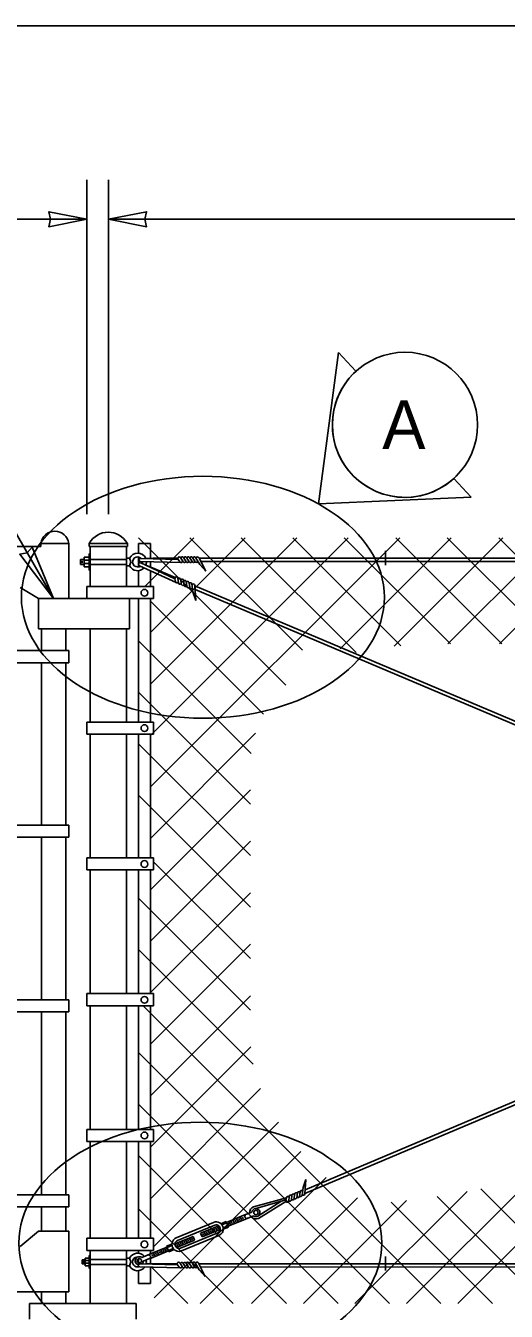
# Model space of a CAD drawing. Extents: x 99862 to 104211, y 98939 to 105076.
# Drawn here: x 101409 to 101607, y 100336 to 100867 of the extents above; entities that cross this region are included whole.
import ezdxf

# ---------------------------------------------------------------- set-up
doc = ezdxf.new("R2010")
doc.units = 0
for name, color, linetype in [('Level 11', 7, 'Continuous'), ('Level 15', 7, 'Continuous'), ('Level 2', 7, 'Continuous'), ('Level 20', 7, 'Continuous'), ('Level 4', 7, 'Continuous'), ('Level 7', 7, 'Continuous'), ('Level 9', 7, 'Continuous')]:
    doc.layers.add(name, color=color, linetype=linetype)

msp = doc.modelspace()

# ---------------------------------------------------------------- linework, layer by layer
at = {"layer": 'Level 11'}
for centre in [(101481.98, 100630.91), (101480.9, 100363.87)]:
    msp.add_ellipse(centre, major_axis=(-75, 0), ratio=0.666667, dxfattribs=at)
at = {"layer": 'Level 15'}
for p, q in [((102151.08, 100867.18), (100287.45, 100867.18)), ((101434.06, 100665.19), (101434.06, 100803.5)), ((101442.98, 100665.19), (101442.98, 100803.5)), ((101434.06, 100787.18), (101009, 100787.18)), ((102151.08, 100787.18), (101442.98, 100787.18)), ((101420.28, 100630.39), (101372.84, 100712.56))]:
    msp.add_line(p, q, dxfattribs=at)
for points in [[(101434.06, 100787.18), (101418.33, 100784.1), (101419.06, 100787.18), (101418.33, 100790.26)], [(101442.98, 100787.18), (101458.7, 100784.1), (101457.97, 100787.18), (101458.7, 100790.26)], [(101420.28, 100630.39), (101411.45, 100651.66), (101409.39, 100649.25), (101406.28, 100648.67)]]:
    msp.add_lwpolyline(points, close=True, dxfattribs=at)
at = {"layer": 'Level 2'}
for p, q in [((101431.33, 100646.54), (101431.33, 100644.46)), ((101431.33, 100646.54), (101432.86, 100646.54)), ((101431.33, 100644.46), (101432.86, 100644.46)), ((101432.14, 100646.02), (101432.14, 100644.98)), ((101432.85, 100644.81), (101434.97, 100644.81)), ((101432.86, 100647.52), (101432.86, 100645.5)), ((101432.86, 100643.48), (101432.86, 100645.5)), ((101432.87, 100646.2), (101434.97, 100646.2)), ((101435.32, 100646.54), (101450.35, 100646.54)), ((101435.32, 100644.46), (101450.35, 100644.46)), ((101451.68, 100647.06), (101452.17, 100645.5)), ((101451.68, 100643.94), (101452.17, 100645.5)), ((101455.74, 100643.96), (101470.93, 100636.94)), ((101456.1, 100645.74), (101472.83, 100645.27)), ((101456.14, 100646.99), (101471.75, 100646.55)), ((101456.26, 100645.1), (101470.44, 100638.55)), ((101458.3, 100646.99), (101461.38, 100647)), ((101458.38, 100644.2), (101461.08, 100643.05)), ((101461.38, 100647), (101471.6, 100647.03)), ((101471.75, 100646.55), (101472.43, 100645.6)), ((101472.75, 100647.29), (101473.76, 100645.57)), ((101473.99, 100647.32), (101475.02, 100645.55)), ((101475.22, 100647.34), (101476.28, 100645.57)), ((101476.46, 100647.36), (101477.49, 100645.64)), ((101477.58, 100645.5), (101477.58, 100645.5)), ((101477.72, 100647.36), (101478.77, 100645.59)), ((101478.98, 100647.34), (101480.66, 100644.48)), ((101480.33, 100647.27), (101483.15, 100641.72)), ((101480.47, 100647), (102110.66, 100647)), ((101480.66, 100644.48), (101483.15, 100641.72)), ((101481.13, 100645.7), (102109.98, 100645.7)), ((101461.08, 100643.05), (101470.49, 100639.04)), ((101470.44, 100638.54), (101470.69, 100637.4)), ((101471.65, 100638.83), (101471.9, 100636.85)), ((101472.8, 100638.36), (101473.06, 100636.33)), ((101473.94, 100637.9), (101474.21, 100635.86)), ((101475.09, 100637.44), (101475.36, 100635.45)), ((101475.38, 100635.28), (101475.38, 100635.28)), ((101476.24, 100636.93), (101476.52, 100634.89)), ((101477.4, 100636.42), (101477.82, 100633.13)), ((101477.82, 100633.13), (101479.01, 100629.61)), ((101478.61, 100635.82), (101479.01, 100629.61)), ((101478.62, 100635.63), (102067.94, 100386.16)), ((101478.72, 100634.17), (102066.84, 100385.21)), ((101796.42, 100499.68), (101524.15, 100384.41)), ((101794.75, 100500.39), (101524.24, 100385.86)), ((101523.36, 100386.85), (101524.51, 100390.25)), ((101524.14, 100384.24), (101524.51, 100390.25)), ((101502.86, 100378.95), (101516.48, 100382.68)), ((101516.25, 100381.57), (101516.48, 100382.68)), ((101517.42, 100381.3), (101517.65, 100383.22)), ((101518.53, 100381.76), (101518.77, 100383.72)), ((101519.63, 100382.21), (101519.89, 100384.19)), ((101520.74, 100382.66), (101521.02, 100384.75)), ((101521.85, 100383.16), (101522.11, 100385.13)), ((101522.97, 100383.66), (101523.36, 100386.85)), ((101503.45, 100378.14), (101516.28, 100381.73)), ((101504.72, 100375.09), (101514.2, 100381.15)), ((101504.91, 100374.12), (101516.3, 100381.09)), ((101470.96, 100366.08), (101486.36, 100372.44)), ((101489.43, 100371.91), (101491.62, 100372.81)), ((101491.62, 100372.81), (101492.57, 100370.5)), ((101491.78, 100372.43), (101498.95, 100375.4)), ((101492.18, 100372.15), (101492.5, 100371.38)), ((101492.41, 100370.89), (101499.59, 100373.86)), ((101492.79, 100372.85), (101493.43, 100371.31)), ((101493.72, 100372.78), (101494.04, 100372.01)), ((101494.33, 100373.49), (101494.97, 100371.95)), ((101495.26, 100373.42), (101495.58, 100372.65)), ((101495.87, 100374.12), (101496.51, 100372.58)), ((101496.8, 100374.06), (101497.12, 100373.29)), ((101497.41, 100374.76), (101498.05, 100373.22)), ((101498.34, 100374.69), (101498.66, 100373.92)), ((101498.95, 100375.4), (101502.24, 100376.75)), ((101499.59, 100373.86), (101502.87, 100375.22)), ((101471.44, 100364.92), (101486.84, 100371.29)), ((101472.71, 100361.84), (101488.12, 100368.21)), ((101473.19, 100360.69), (101488.6, 100367.06)), ((101488.49, 100371.07), (101481, 100367.97)), ((101481, 100367.97), (101481.64, 100366.43)), ((101489.13, 100369.53), (101481.64, 100366.43)), ((101481.93, 100367.91), (101482.25, 100367.14)), ((101482.54, 100368.61), (101483.18, 100367.07)), ((101483.47, 100368.54), (101483.79, 100367.77)), ((101484.08, 100369.25), (101484.72, 100367.71)), ((101485.01, 100369.18), (101485.33, 100368.41)), ((101485.62, 100369.88), (101486.26, 100368.34)), ((101486.55, 100369.82), (101486.87, 100369.05)), ((101487.16, 100370.52), (101487.8, 100368.98)), ((101488.09, 100370.45), (101488.41, 100369.68)), ((101490.39, 100369.6), (101492.57, 100370.5)), ((101467.14, 100362.24), (101459.97, 100359.28)), ((101466.13, 100361.82), (101466.77, 100360.28)), ((101469.16, 100363.53), (101466.98, 100362.63)), ((101466.98, 100362.63), (101467.93, 100360.32)), ((101467.06, 100361.76), (101467.38, 100360.99)), ((101470.43, 100363.6), (101477.92, 100366.7)), ((101471.07, 100362.06), (101478.56, 100365.16)), ((101471.15, 100363.45), (101471.47, 100362.68)), ((101471.76, 100364.15), (101472.4, 100362.61)), ((101472.69, 100364.09), (101473.01, 100363.32)), ((101473.3, 100364.79), (101473.94, 100363.25)), ((101474.23, 100364.72), (101474.55, 100363.95)), ((101474.84, 100365.43), (101475.48, 100363.89)), ((101475.77, 100365.36), (101476.09, 100364.59)), ((101476.38, 100366.06), (101477.02, 100364.52)), ((101477.31, 100366), (101477.63, 100365.23)), ((101477.92, 100366.7), (101478.56, 100365.16)), ((101432.11, 100356.94), (101432.11, 100355.27)), ((101432.11, 100356.94), (101433.33, 100356.94)), ((101432.76, 100356.52), (101432.76, 100355.69)), ((101433.33, 100357.72), (101433.33, 100356.11)), ((101433.33, 100354.49), (101433.33, 100356.11)), ((101433.34, 100356.66), (101435.02, 100356.66)), ((101435.32, 100357.15), (101450.35, 100357.15)), ((101451.68, 100357.67), (101452.16, 100356.11)), ((101451.68, 100354.55), (101452.16, 100356.11)), ((101459.99, 100359.28), (101456.7, 100357.93)), ((101460.63, 100357.75), (101457.34, 100356.39)), ((101467.78, 100360.7), (101460.61, 100357.74)), ((101460.9, 100359.21), (101461.22, 100358.44)), ((101461.51, 100359.91), (101462.15, 100358.37)), ((101462.44, 100359.85), (101462.76, 100359.08)), ((101463.05, 100360.55), (101463.69, 100359.01)), ((101463.98, 100360.48), (101464.3, 100359.71)), ((101464.59, 100361.19), (101465.23, 100359.65)), ((101465.52, 100361.12), (101465.84, 100360.35)), ((101470.12, 100361.22), (101467.93, 100360.32)), ((101432.11, 100355.27), (101433.33, 100355.27)), ((101433.32, 100355.55), (101435.02, 100355.55)), ((101450.35, 100355.07), (101435.32, 100355.07)), ((101455.87, 100354.07), (101472.59, 100353.66)), ((101455.9, 100355.32), (101471.51, 100354.94)), ((101458.53, 100355.33), (101461.13, 100355.35)), ((101461.13, 100355.35), (101471.36, 100355.41)), ((101471.51, 100354.94), (101472.19, 100353.98)), ((101472.51, 100355.68), (101473.52, 100353.96)), ((101473.74, 100355.71), (101474.78, 100353.95)), ((101474.98, 100355.74), (101476.04, 100353.97)), ((101476.21, 100355.77), (101477.34, 100353.91)), ((101477.47, 100355.76), (101478.53, 100354)), ((101478.74, 100355.75), (101480.43, 100352.89)), ((101480.09, 100355.68), (101482.92, 100350.15)), ((101480.26, 100355.34), (102109.78, 100355.28)), ((101480.43, 100352.89), (101482.92, 100350.15)), ((101480.93, 100354.04), (102109.1, 100353.98))]:
    msp.add_line(p, q, dxfattribs=at)
for points in [[(101434.97, 100647.52), (101434.97, 100648.77), (101435.28, 100648.77)], [(101434.97, 100643.48), (101434.97, 100642.23), (101435.28, 100642.23), (101435.28, 100648.77)], [(101434.97, 100645.5), (101434.97, 100647.52), (101432.86, 100647.52)], [(101434.97, 100645.5), (101434.97, 100643.48), (101432.86, 100643.48)], [(101450.35, 100646.54), (101450.35, 100647.06), (101451.68, 100647.06)], [(101450.35, 100644.46), (101450.35, 100643.94), (101451.68, 100643.94)], [(101489.83, 100371.46), (101491.83, 100372.29)], [(101490.36, 100370.2), (101492.35, 100371.03)], [(101469.2, 100362.93), (101467.2, 100362.1)], [(101469.72, 100361.67), (101467.72, 100360.84)], [(101435.02, 100356.11), (101435.02, 100357.72), (101433.33, 100357.72)], [(101435.02, 100356.11), (101435.02, 100354.49), (101433.33, 100354.49)], [(101435.02, 100357.72), (101435.02, 100358.72), (101435.27, 100358.72)], [(101435.02, 100354.49), (101435.02, 100353.49), (101435.27, 100353.49), (101435.27, 100358.72)], [(101450.35, 100357.15), (101450.35, 100357.67), (101451.68, 100357.67)], [(101450.35, 100355.07), (101450.35, 100354.55), (101451.68, 100354.55)]]:
    msp.add_lwpolyline(points, dxfattribs=at)
for centre in [(101503.89, 100376.54), (101455.69, 100356.6)]:
    msp.add_circle(centre, 0.916, dxfattribs=at)
for centre, radius, start, end in [((101454.98, 100645.5), 3.64, 23.0497, 154.6231), ((101454.98, 100645.5), 3.64, 205.3769, 318.0032), ((101454.98, 100645.5), 2.08, 45.2715, 288.2696), ((101455.99, 100644.54), 0.625, 66.9537, 246.9537), ((101456.1, 100646.36), 0.625, 90.1491, 270.1491), ((101454.98, 100645.5), 2.08, 288.2696, 304.0348), ((101454.98, 100645.5), 2.08, 339.9416, 5.5001), ((101454.98, 100645.5), 3.64, 337.9108, 2.3872), ((101472.22, 100646.96), 0.625, 32.0393, 221.1886), ((101472.98, 100645.88), 0.625, 206.9269, 354.8752), ((101473.47, 100646.97), 0.625, 34.0124, 167.2416), ((101474.3, 100645.88), 0.625, 210.1721, 347.2992), ((101474.72, 100646.97), 0.625, 36.7719, 167.2992), ((101475.55, 100645.89), 0.625, 212.7334, 348.3724), ((101475.97, 100646.97), 0.625, 38.6782, 167.4312), ((101476.82, 100645.89), 0.625, 210.6764, 347.4715), ((101477.22, 100646.98), 0.625, 37.4612, 167.5509), ((101478.07, 100645.89), 0.625, 203.3194, 346.8486), ((101478.47, 100646.98), 0.625, 35.0227, 167.4721), ((101479.31, 100645.91), 0.625, 210.7861, 345.4504), ((101479.77, 100646.98), 0.625, 26.9068, 173.7455), ((101471.04, 100638.74), 0.625, 8.8439, 197.9932), ((101472.19, 100638.25), 0.625, 10.817, 144.0462), ((101473.34, 100637.76), 0.625, 13.5765, 144.1038), ((101474.49, 100637.27), 0.625, 15.4829, 144.2358), ((101471.31, 100637.44), 0.625, 183.7315, 331.6798), ((101472.52, 100636.93), 0.625, 186.9767, 324.1038), ((101473.67, 100636.44), 0.625, 189.538, 325.177), ((101474.84, 100635.94), 0.625, 187.481, 324.2761), ((101475.64, 100636.78), 0.625, 14.2658, 144.3555), ((101475.99, 100635.45), 0.625, 180.124, 323.6532), ((101476.79, 100636.29), 0.625, 11.8273, 144.2767), ((101477.14, 100634.98), 0.625, 187.5907, 322.255), ((101477.99, 100635.78), 0.625, 3.7115, 150.5502), ((101517.08, 100382.64), 0.605, 28.5599, 176.5082), ((101518.25, 100383.15), 0.605, 36.1359, 173.2631), ((101519.36, 100383.63), 0.605, 35.0627, 175.5196), ((101520.16, 100382.82), 0.605, 216.0039, 0.1158), ((101520.49, 100384.11), 0.605, 35.9637, 172.7588), ((101521.27, 100383.3), 0.605, 215.8843, 359.324), ((101521.6, 100384.59), 0.605, 36.5865, 180.1158), ((101522.38, 100383.78), 0.605, 215.9631, 357.5858), ((101522.71, 100385.05), 0.605, 37.9847, 172.649), ((101523.54, 100384.28), 0.605, 209.6896, 356.5283), ((101503.89, 100376.54), 2.63, 112.9687, 183.9611), ((101503.89, 100376.54), 1.67, 232.4657, 172.4657), ((101516.82, 100381.39), 0.605, 162.2466, 355.1304), ((101517.93, 100381.87), 0.605, 216.1935, 356.7986), ((101519.04, 100382.35), 0.605, 216.1359, 358.8543), ((101487.47, 100369.75), 2.92, 6.1532, 112.4677), ((101500.06, 100374.95), 0.833, 112.4657, 292.4657), ((101503.89, 100376.54), 2.63, 220.9704, 292.9687), ((101487.47, 100369.75), 1.67, 349.3809, 112.4675), ((101487.47, 100369.75), 1.67, 292.4657, 352.4644), ((101487.47, 100369.75), 2.92, 292.4657, 8.942), ((101472.08, 100363.38), 2.92, 112.4638, 217.9828), ((101472.08, 100363.38), 2.92, 215.9905, 292.4657), ((101472.08, 100363.38), 1.67, 112.464, 241.5718), ((101472.08, 100363.38), 1.67, 232.4657, 292.4657), ((101454.97, 100356.11), 3.64, 38.6945, 154.6231), ((101454.97, 100356.11), 2.08, 85.0186, 287.4299), ((101455.69, 100356.6), 1.67, 52.4657, 256.9058), ((101455.69, 100356.6), 1.67, 309.0275, 352.4657), ((101454.97, 100356.11), 3.64, 346.449, 12.2317), ((101459.52, 100358.19), 0.833, 292.4657, 112.4657), ((101454.97, 100356.11), 3.64, 205.3769, 324.6217), ((101455.86, 100354.69), 0.625, 90.3612, 270.3612), ((101454.97, 100356.11), 2.08, 337.5058, 344.4441), ((101471.98, 100355.35), 0.625, 32.2514, 221.4006), ((101472.74, 100354.27), 0.625, 207.139, 355.0873), ((101473.23, 100355.36), 0.625, 34.2245, 167.4537), ((101474.06, 100354.28), 0.627, 210.4381, 347.5653), ((101474.48, 100355.37), 0.625, 36.984, 167.5113), ((101475.31, 100354.29), 0.625, 212.9455, 348.5845), ((101475.73, 100355.37), 0.625, 23.5314, 167.6433), ((101476.57, 100354.29), 0.627, 210.9641, 347.7591), ((101476.98, 100355.38), 0.625, 37.6733, 167.763), ((101477.83, 100354.3), 0.625, 218.8903, 347.0607), ((101478.23, 100355.39), 0.625, 35.2348, 167.6842), ((101479.07, 100354.32), 0.626, 211.0453, 345.7096), ((101479.53, 100355.4), 0.625, 27.1189, 173.9576)]:
    msp.add_arc(centre, radius, start, end, dxfattribs=at)
at = {"layer": 'Level 4'}
for p, q in [((101516.21, 100594.62), (101455.31, 100655.53)), ((101458.11, 100635.45), (101478.19, 100655.53)), ((101460.4, 100552.61), (101563.31, 100655.53)), ((101460.4, 100573.88), (101542.04, 100655.53)), ((101460.4, 100616.45), (101499.47, 100655.53)), ((101460.4, 100595.17), (101520.76, 100655.53)), ((101523.1, 100609.01), (101476.59, 100655.53)), ((101545.3, 100608.03), (101497.8, 100655.53)), ((101563.73, 100610.87), (101519.07, 100655.53)), ((101538.68, 100609.61), (101584.6, 100655.53)), ((101584.28, 100611.6), (101540.35, 100655.53)), ((101560.96, 100610.62), (101605.88, 100655.53)), ((101605.54, 100611.64), (101561.65, 100655.53)), ((101626.16, 100612.28), (101582.91, 100655.53)), ((101583.22, 100611.59), (101627.16, 100655.53)), ((101646.59, 100613.13), (101604.19, 100655.53)), ((101604.53, 100611.62), (101648.44, 100655.53)), ((101557.36, 100644.12), (101557.36, 100650.06)), ((101507.01, 100582.54), (101460.4, 100629.16)), ((101501.95, 100566.32), (101455.36, 100612.91)), ((101501.62, 100545.37), (101455.36, 100591.63)), ((101460.4, 100531.32), (101503.76, 100574.69)), ((101501.62, 100524.1), (101455.36, 100570.36)), ((101501.62, 100502.84), (101455.36, 100549.15)), ((101460.4, 100510.05), (101501.62, 100551.27)), ((101460.37, 100488.76), (101501.62, 100530)), ((101501.62, 100481.53), (101461.62, 100521.53)), ((101501.62, 100460.25), (101455.36, 100506.51)), ((101460.11, 100467.21), (101501.62, 100508.71)), ((101502.75, 100437.84), (101455.36, 100485.23)), ((101460.4, 100446.24), (101501.62, 100487.45)), ((101460.4, 100424.93), (101501.62, 100466.16)), ((101580.36, 100338.95), (101457.41, 100461.91)), ((101559.09, 100338.95), (101455.36, 100442.68)), ((101460.4, 100403.65), (101501.75, 100445.01)), ((101460.4, 100382.38), (101505.82, 100427.8)), ((101537.81, 100338.95), (101455.36, 100421.39)), ((101461.62, 100362.32), (101513.24, 100413.94)), ((101516.54, 100338.95), (101455.36, 100400.12)), ((101461.81, 100341.24), (101522.42, 100401.84)), ((101587.38, 100338.95), (101643.47, 100395.04)), ((101480.79, 100338.95), (101532.84, 100390.99)), ((101566.11, 100338.95), (101617.56, 100390.4)), ((101544.82, 100338.95), (101591.13, 100385.26)), ((101622.93, 100338.95), (101578.72, 100383.16)), ((101644.2, 100338.95), (101596.83, 100386.32)), ((101494.47, 100338.95), (101455.36, 100378.06)), ((101502.1, 100338.95), (101545.81, 100382.64)), ((101523.55, 100338.95), (101566.07, 100381.47)), ((101601.65, 100338.95), (101559.74, 100380.85)), ((101557.36, 100352.53), (101557.36, 100358.39)), ((101475.7, 100338.95), (101460.73, 100353.91))]:
    msp.add_line(p, q, dxfattribs=at)
at = {"layer": 'Level 7'}
for p, q in [((101415.02, 100651.94), (101398.98, 100651.94)), ((101415.02, 100651.94), (101415.02, 100653.19)), ((101415.02, 100653.19), (101426.54, 100653.19)), ((101426.54, 100630.39), (101426.54, 100653.19)), ((101434.95, 100653.19), (101450.75, 100653.19)), ((101434.95, 100653.19), (101434.95, 100651.94)), ((101450.75, 100651.94), (101434.95, 100651.94)), ((101435.32, 100635.4), (101435.32, 100651.94)), ((101450.35, 100635.4), (101450.35, 100651.94)), ((101450.75, 100653.19), (101450.75, 100651.94)), ((101460.37, 100653.19), (101455.36, 100653.19)), ((101455.36, 100649.13), (101455.36, 100653.19)), ((101460.37, 100646.97), (101460.37, 100653.19)), ((101455.36, 100643.45), (101455.36, 100647.55)), ((101460.37, 100643.35), (101460.37, 100645.6)), ((101455.36, 100635.4), (101455.36, 100641.88)), ((101460.37, 100635.4), (101460.37, 100641.82)), ((101406.44, 100634.94), (101414.01, 100630.39)), ((101461.62, 100635.4), (101434.06, 100635.4)), ((101434.06, 100630.39), (101434.06, 100635.4)), ((101461.62, 100630.39), (101461.62, 100635.4)), ((101426.54, 100630.39), (101414.01, 100630.39)), ((101414.01, 100617.87), (101414.01, 100630.39)), ((101461.62, 100630.39), (101426.54, 100630.39)), ((101451.6, 100617.87), (101451.6, 100630.39)), ((101455.36, 100579.28), (101455.36, 100630.39)), ((101460.37, 100579.28), (101460.37, 100630.39)), ((101451.6, 100617.87), (101414.01, 100617.87)), ((101415.27, 100608.85), (101415.27, 100617.87)), ((101425.3, 100608.85), (101425.3, 100617.87)), ((101435.32, 100579.28), (101435.32, 100617.87)), ((101450.35, 100579.28), (101450.35, 100617.87)), ((101426.54, 100608.85), (101400.18, 100608.85)), ((101426.54, 100608.85), (101426.54, 100603.83)), ((101426.54, 100603.83), (101400.18, 100603.83)), ((101415.27, 100536.69), (101415.27, 100603.83)), ((101425.3, 100536.69), (101425.3, 100603.83)), ((101461.62, 100579.28), (101434.06, 100579.28)), ((101434.06, 100579.28), (101434.06, 100574.27)), ((101461.62, 100574.27), (101434.06, 100574.27)), ((101435.32, 100523.16), (101435.32, 100574.27)), ((101450.35, 100523.16), (101450.35, 100574.27)), ((101455.36, 100523.16), (101455.36, 100574.27)), ((101460.37, 100523.16), (101460.37, 100574.27)), ((101461.62, 100574.27), (101461.62, 100579.28)), ((101426.54, 100536.69), (101400.18, 100536.69)), ((101426.54, 100531.68), (101400.18, 100531.68)), ((101415.27, 100464.53), (101415.27, 100531.68)), ((101425.3, 100464.53), (101425.3, 100531.68)), ((101426.54, 100536.69), (101426.54, 100531.68)), ((101461.62, 100523.16), (101434.06, 100523.16)), ((101434.06, 100523.16), (101434.06, 100518.15)), ((101461.62, 100518.15), (101461.62, 100523.16)), ((101461.62, 100518.15), (101434.06, 100518.15)), ((101435.32, 100467.03), (101435.32, 100518.15)), ((101450.35, 100467.03), (101450.35, 100518.15)), ((101455.36, 100467.03), (101455.36, 100518.15)), ((101460.37, 100467.03), (101460.37, 100518.15)), ((101426.54, 100464.53), (101400.18, 100464.53)), ((101426.54, 100464.53), (101426.54, 100459.52)), ((101461.62, 100467.03), (101434.06, 100467.03)), ((101434.06, 100467.03), (101434.06, 100462.02)), ((101461.62, 100462.02), (101461.62, 100467.03)), ((101426.54, 100459.52), (101400.18, 100459.52)), ((101415.27, 100383.85), (101415.27, 100459.52)), ((101425.3, 100383.85), (101425.3, 100459.52)), ((101461.62, 100462.02), (101434.06, 100462.02)), ((101435.32, 100410.91), (101435.32, 100462.02)), ((101450.35, 100410.91), (101450.35, 100462.02)), ((101455.36, 100410.91), (101455.36, 100462.02)), ((101460.37, 100410.91), (101460.37, 100462.02)), ((101461.62, 100410.91), (101434.06, 100410.91)), ((101434.06, 100410.91), (101434.06, 100405.9)), ((101461.62, 100405.9), (101461.62, 100410.91)), ((101461.62, 100405.9), (101434.06, 100405.9)), ((101435.32, 100365.91), (101435.32, 100405.9)), ((101450.35, 100365.91), (101450.35, 100405.9)), ((101455.36, 100365.91), (101455.36, 100405.9)), ((101460.37, 100365.91), (101460.37, 100405.9)), ((101426.54, 100383.85), (101400.18, 100383.85)), ((101426.54, 100383.85), (101426.54, 100378.84)), ((101426.54, 100378.84), (101400.18, 100378.84)), ((101415.27, 100368.82), (101415.27, 100378.84)), ((101425.3, 100368.82), (101425.3, 100378.84)), ((101414.01, 100368.82), (101406.44, 100362.5)), ((101414.01, 100368.82), (101426.54, 100368.82)), ((101426.54, 100343.76), (101426.54, 100368.82)), ((101461.62, 100365.91), (101434.06, 100365.91)), ((101434.06, 100365.91), (101434.06, 100360.9)), ((101461.62, 100360.9), (101461.62, 100365.91)), ((101461.62, 100360.9), (101434.06, 100360.9)), ((101435.32, 100339), (101435.32, 100360.9)), ((101450.35, 100339), (101450.35, 100360.9)), ((101455.36, 100359.73), (101455.36, 100360.9)), ((101455.36, 100355.75), (101455.36, 100357.46)), ((101460.37, 100359.44), (101460.37, 100360.9)), ((101460.37, 100355.31), (101460.37, 100357.64)), ((101455.36, 100354.06), (101455.36, 100354.31)), ((101455.36, 100347.17), (101455.36, 100352.48)), ((101460.37, 100347.17), (101460.37, 100353.92)), ((101455.36, 100347.17), (101460.37, 100347.17)), ((101398.98, 100343.76), (101426.54, 100343.76)), ((101415.27, 100343.76), (101415.27, 100339)), ((101425.3, 100343.76), (101425.3, 100339)), ((101410.26, 100339), (101410.26, 100332.49)), ((101410.26, 100339), (101454.36, 100339)), ((101454.36, 100332.49), (101454.36, 100339))]:
    msp.add_line(p, q, dxfattribs=at)
for centre in [(101457.82, 100632.76), (101457.82, 100576.81), (101457.82, 100520.6), (101457.82, 100464.47), (101457.82, 100408.42), (101457.82, 100363.39)]:
    msp.add_circle(centre, 1.41, dxfattribs=at)
msp.add_arc((101420.78, 100652.38), 5.82, 7.9818, 172.0182, dxfattribs=at)
msp.add_ellipse((101442.85, 100647.16), major_axis=(0, 10.64), ratio=0.901076, start_param=5.315025, end_param=7.251346, dxfattribs=at)
at = {"layer": 'Level 9'}
for p, q in [((101538.07, 100732.15), (101529.7, 100669.48)), ((101545.22, 100724.32), (101538.07, 100732.15)), ((101592.87, 100672.23), (101585.71, 100680.05)), ((101529.7, 100669.48), (101592.87, 100672.23))]:
    msp.add_line(p, q, dxfattribs=at)
msp.add_circle((101565.47, 100702.19), 30, dxfattribs=at)
msp.add_arc((101565.47, 100702.19), 30, 132.4424, 312.4468, dxfattribs=at)

# ---------------------------------------------------------------- texts
at = {"layer": 'Level 20'}
msp.add_text('A', height=20, dxfattribs=at).set_placement((101556.1, 100692.25))

doc.saveas('drawing.dxf')
